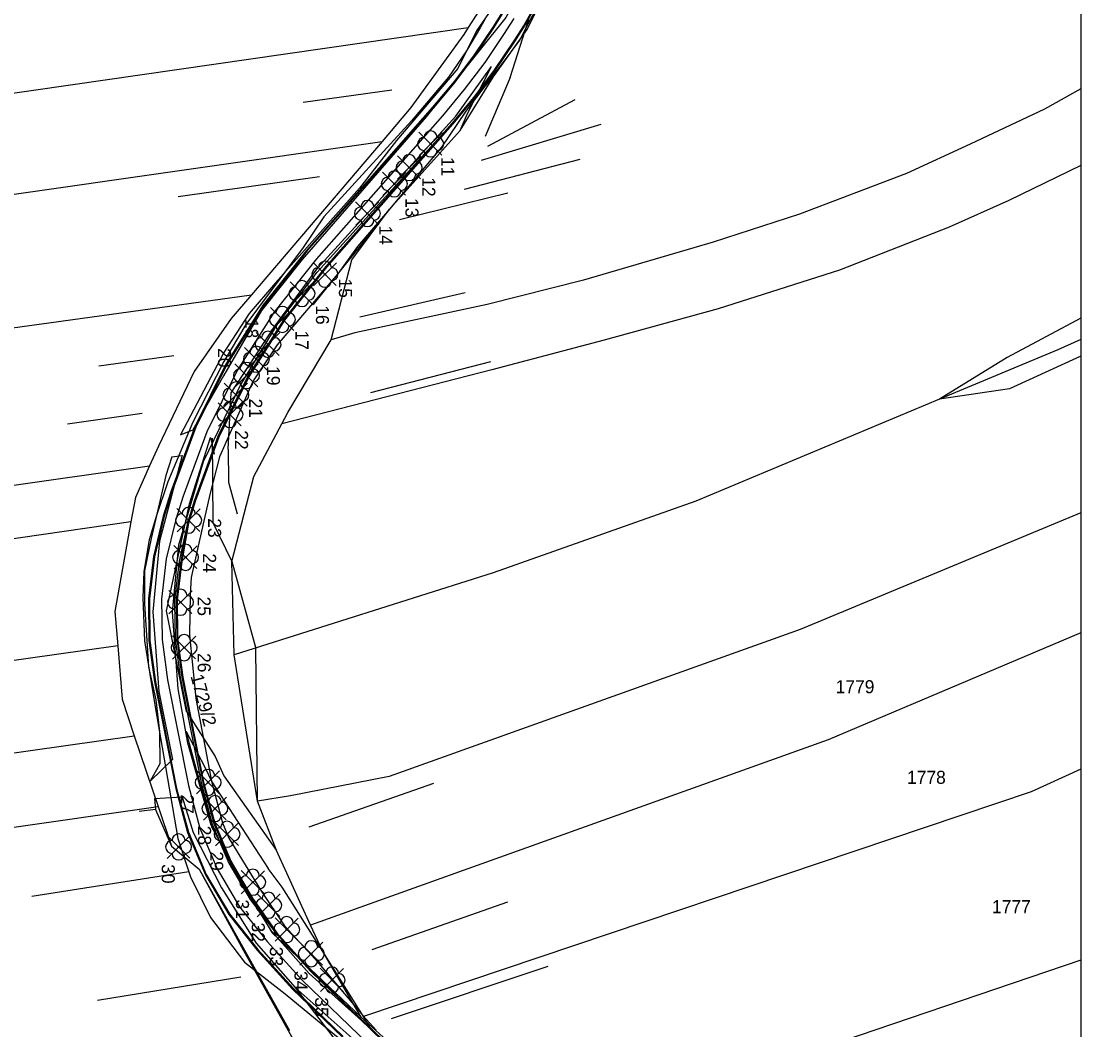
# Model space of a CAD drawing. Extents: x -601800 to -601487, y -1201912 to -1200862.
# Drawn here: x -601649.2 to -601486.7, y -1201238.4 to -1201083.7 of the extents above; entities that cross this region are included whole.
import ezdxf

# ---------------------------------------------------------------- set-up
doc = ezdxf.new("R2010")
doc.units = 0
for name, color, linetype in [('Hranice parcel', 7, 'Continuous'), ('Parcelní čísla', 7, 'Continuous'), ('popis', 7, 'Continuous'), ('u_hrany', 7, 'Continuous'), ('U_keř', 7, 'Continuous'), ('u_návrh', 7, 'Continuous'), ('u_osa', 7, 'Continuous'), ('u_strom', 7, 'Continuous'), ('u_terénní úpravy', 7, 'Continuous'), ('x_rám', 7, 'Continuous')]:
    doc.layers.add(name, color=color, linetype=linetype)

msp = doc.modelspace()

# ---------------------------------------------------------------- linework, layer by layer
at = {"layer": 'Hranice parcel'}
for p, q in [((-601593.88, -1201102.11), (-601613.91, -1201125.63)), ((-601783.66, -1201173.9), (-601629.54, -1201151.87)), ((-601632.4, -1201160.49), (-601783.66, -1201182.11)), ((-601634.44, -1201179.47), (-601783.66, -1201200.8)), ((-601612.99, -1201203.33), (-601616.59, -1201180.86)), ((-601783.66, -1201214.97), (-601631.89, -1201193.28)), ((-601631.89, -1201193.28), (-601628.22, -1201204.11)), ((-601783.66, -1201226.33), (-601628.22, -1201204.11)), ((-601595.54, -1201238.27), (-601596.75, -1201236.33))]:
    msp.add_line(p, q, dxfattribs=at)
for points in [[(-601571.88, -1201047.94), (-601570.74, -1201062.64), (-601572.44, -1201071.88), (-601580.66, -1201084.64)], [(-601576.81, -1201092.27), (-601571.6, -1201084.92), (-601566.85, -1201075.32), (-601566.81, -1201075.18)], [(-601783.66, -1201113.35), (-601714.46, -1201103.92), (-601580.66, -1201084.64)], [(-601580.66, -1201084.64), (-601581.35, -1201085.7), (-601589.47, -1201096.93), (-601593.88, -1201102.11)], [(-601595.54, -1201238.27), (-601605.07, -1201229.77), (-601610.77, -1201223.3), (-601615.91, -1201215.13), (-601620.08, -1201206.99), (-601623.67, -1201194.4), (-601625.15, -1201186.11), (-601626.02, -1201174.3), (-601625.06, -1201163.98), (-601621.25, -1201151.23), (-601615.58, -1201139.5), (-601609.8, -1201129.97), (-601603.81, -1201122.15), (-601584.37, -1201100.7), (-601576.81, -1201092.27)], [(-601601.67, -1201132.55), (-601598.51, -1201120.27), (-601592.73, -1201112.5), (-601581.87, -1201100.46), (-601576.81, -1201092.27)], [(-601486.66, -1201094.03), (-601492.25, -1201097.19), (-601503.64, -1201102.54), (-601513.42, -1201107.04), (-601529.8, -1201113.29), (-601543.07, -1201117.55), (-601562.98, -1201123.4), (-601577.77, -1201127.14), (-601598.06, -1201131.5), (-601601.67, -1201132.55)], [(-601783.66, -1201128.79), (-601712.92, -1201119.14), (-601593.88, -1201102.11)], [(-601486.66, -1201105.79), (-601497.71, -1201111.2), (-601506.84, -1201115.28), (-601523.69, -1201121.87), (-601542.28, -1201127.81), (-601559.8, -1201132.59), (-601577.05, -1201137.14), (-601609.27, -1201145.43)], [(-601783.66, -1201149.13), (-601718.74, -1201140.14), (-601613.91, -1201125.63)], [(-601613.91, -1201125.63), (-601617.03, -1201129.29), (-601622.71, -1201137.41), (-601628.18, -1201148.87), (-601629.54, -1201151.87)], [(-601486.66, -1201129.2), (-601497.94, -1201135.28), (-601508.35, -1201141.67)], [(-601609.27, -1201145.43), (-601608.36, -1201143.71), (-601601.67, -1201132.55)], [(-601486.66, -1201132.51), (-601490.19, -1201134.06), (-601508.35, -1201141.67)], [(-601486.66, -1201135.06), (-601497.59, -1201140.05), (-601508.35, -1201141.67)], [(-601508.35, -1201141.67), (-601545.72, -1201157.32), (-601576.81, -1201168.3), (-601616.59, -1201180.86)], [(-601616.59, -1201180.86), (-601616.93, -1201166.56), (-601613.57, -1201153.51), (-601609.27, -1201145.43)], [(-601629.54, -1201151.87), (-601631.73, -1201156.73), (-601632.4, -1201160.49)], [(-601486.66, -1201159.11), (-601529.7, -1201176.99), (-601592.77, -1201199.55), (-601607.91, -1201202.49), (-601612.99, -1201203.33)], [(-601632.4, -1201160.49), (-601634.87, -1201174.22), (-601634.44, -1201179.47)], [(-601486.66, -1201177.47), (-601525.44, -1201193.92), (-601604.85, -1201222.33)], [(-601634.44, -1201179.47), (-601633.78, -1201187.68), (-601631.89, -1201193.28)], [(-601486.66, -1201198.41), (-601494.28, -1201201.89), (-601596.75, -1201236.33)], [(-601628.22, -1201204.11), (-601626.16, -1201210.2), (-601621.94, -1201213.75), (-601608.09, -1201238.51)], [(-601604.85, -1201222.33), (-601610.09, -1201210.89), (-601612.99, -1201203.33)], [(-601596.75, -1201236.33), (-601602.98, -1201226.4), (-601604.85, -1201222.33)], [(-601486.66, -1201227.7), (-601575.76, -1201257.99)], [(-601575.76, -1201257.99), (-601583.56, -1201248.88), (-601595.54, -1201238.27)]]:
    msp.add_lwpolyline(points, dxfattribs=at)
at = {"layer": 'u_hrany'}
for points in [[(-601567.64, -1201054.11), (-601568.91, -1201060.36), (-601570.43, -1201066.96), (-601575.8, -1201079.91), (-601579.37, -1201085.15), (-601582.23, -1201090.92), (-601591.68, -1201101.99), (-601597.36, -1201109.27), (-601610.21, -1201123.79), (-601614.29, -1201128.53), (-601618.14, -1201134.51), (-601624.79, -1201147.13)], [(-601565.88, -1201054.02), (-601566.84, -1201062.55), (-601567.35, -1201066.39), (-601569.99, -1201074.28), (-601574.88, -1201083.12), (-601587.13, -1201098.35), (-601606.12, -1201120.23), (-601612.39, -1201128.07), (-601618.22, -1201138.07), (-601622.89, -1201146.38)], [(-601574.23, -1201092.29), (-601571.17, -1201082.7)], [(-601617.03, -1201140.66), (-601610.42, -1201130.59), (-601603.71, -1201121.52), (-601582.56, -1201098.24), (-601577.06, -1201090.61)], [(-601580.79, -1201097.85), (-601577.06, -1201090.61)], [(-601574.23, -1201092.29), (-601578.08, -1201101.35)], [(-601592.4, -1201094.26), (-601606, -1201096.15)], [(-601577.67, -1201102.82), (-601564.27, -1201095.7)], [(-601581.87, -1201100.46), (-601580.79, -1201097.85)], [(-601578.6, -1201104.97), (-601560.28, -1201099.46)], [(-601581.87, -1201100.46), (-601592.73, -1201112.5), (-601604.43, -1201127.11)], [(-601581.24, -1201109.45), (-601563.46, -1201104.84)], [(-601603.47, -1201107.56), (-601625.16, -1201110.59)], [(-601591.19, -1201114.1), (-601574.59, -1201110.02)], [(-601597.3, -1201129.03), (-601581.12, -1201125.27)], [(-601625.85, -1201134.98), (-601637.32, -1201136.61)], [(-601595.6, -1201140.62), (-601577.2, -1201135.87)], [(-601617.5, -1201149.31), (-601617.03, -1201140.66)], [(-601630.71, -1201143.86), (-601642.13, -1201145.5)], [(-601624.79, -1201147.13), (-601622.89, -1201146.38)], [(-601623.9, -1201189.57), (-601626.94, -1201174.12), (-601623.43, -1201157.73), (-601620.2, -1201147.52)], [(-601620.2, -1201147.52), (-601619.64, -1201150.1)], [(-601619.93, -1201147.64), (-601619.86, -1201160.56)], [(-601626.15, -1201150.5), (-601627.05, -1201153.34), (-601629.3, -1201163.03), (-601630.32, -1201167.99), (-601630.35, -1201173.03), (-601629.69, -1201182.73), (-601628.6, -1201187.76), (-601628.03, -1201192.62), (-601627.99, -1201197.6), (-601629.47, -1201200.24)], [(-601624.54, -1201150.28), (-601628.02, -1201163.41), (-601629.03, -1201174.27), (-601628.13, -1201186.48), (-601626.01, -1201196.91)], [(-601626.15, -1201150.5), (-601624.54, -1201150.28)], [(-601617.5, -1201149.31), (-601617.43, -1201154.4), (-601616.11, -1201159.25)], [(-601619.86, -1201160.56), (-601616.93, -1201166.56), (-601613.25, -1201179.88)], [(-601610.09, -1201210.89), (-601612.99, -1201203.33), (-601613.25, -1201179.88)], [(-601623.9, -1201189.57), (-601619.5, -1201196.44)], [(-601623.94, -1201192.61), (-601621.05, -1201198.08)], [(-601566.78, -1201268.44), (-601572.76, -1201260.92), (-601583.6, -1201248.74), (-601597.1, -1201236.47), (-601610.74, -1201223.52), (-601619.92, -1201207.39), (-601623.94, -1201192.61)], [(-601629.47, -1201200.24), (-601626.01, -1201196.91)], [(-601619.5, -1201196.44), (-601618.14, -1201199.44), (-601610.09, -1201210.89)], [(-601621.05, -1201198.08), (-601619.99, -1201200.37), (-601611.36, -1201213.65)], [(-601605.06, -1201207.28), (-601585.93, -1201200.55)], [(-601628.77, -1201202.9), (-601624.54, -1201202.66)], [(-601624.54, -1201202.66), (-601622.88, -1201208.1), (-601618.52, -1201216.62), (-601613.18, -1201225.1), (-601607.2, -1201231.89), (-601597.53, -1201240.51), (-601585.7, -1201250.99), (-601570.84, -1201268.04), (-601567.28, -1201275.16), (-601563.64, -1201286.39)], [(-601628.77, -1201202.9), (-601628.64, -1201204.61), (-601631.13, -1201204.92)], [(-601628.64, -1201204.61), (-601626.16, -1201210.2), (-601621.94, -1201213.75), (-601615.14, -1201226.21), (-601601.18, -1201251.22)], [(-601597.1, -1201236.47), (-601602.98, -1201226.4), (-601609.22, -1201216.5), (-601611.36, -1201213.65)], [(-601623.51, -1201214.16), (-601647.59, -1201217.93)], [(-601595.37, -1201226.07), (-601574.59, -1201218.74)], [(-601592.42, -1201236.64), (-601568.39, -1201228.61)], [(-601615.54, -1201230.32), (-601637.56, -1201233.91)], [(-601607.2, -1201231.89), (-601599.12, -1201242.46), (-601589.13, -1201252.96), (-601570.11, -1201279.18), (-601565.04, -1201291.14), (-601564.82, -1201293.65)]]:
    msp.add_lwpolyline(points, dxfattribs=at)
at = {"layer": 'U_keř'}
for p, q in [((-601588.23, -1201100.69), (-601584.69, -1201104.23)), ((-601584.66, -1201100.73), (-601588.19, -1201104.26)), ((-601591.52, -1201104.32), (-601587.99, -1201107.85)), ((-601587.95, -1201104.35), (-601591.49, -1201107.89)), ((-601593.8, -1201106.82), (-601590.26, -1201110.36)), ((-601590.23, -1201106.86), (-601593.76, -1201110.39)), ((-601597.93, -1201111.37), (-601594.39, -1201114.9)), ((-601594.35, -1201111.4), (-601597.89, -1201114.94)), ((-601604.45, -1201120.68), (-601600.92, -1201124.22)), ((-601600.88, -1201120.72), (-601604.42, -1201124.25)), ((-601607.97, -1201123.66), (-601604.43, -1201127.19)), ((-601604.4, -1201123.69), (-601607.93, -1201127.23)), ((-601610.97, -1201127.61), (-601607.43, -1201131.14)), ((-601607.4, -1201127.64), (-601610.93, -1201131.18)), ((-601613.17, -1201131.44), (-601609.64, -1201134.97)), ((-601609.6, -1201131.47), (-601613.14, -1201135.01)), ((-601614.97, -1201133.71), (-601611.43, -1201137.25)), ((-601611.4, -1201133.75), (-601614.93, -1201137.28)), ((-601616.49, -1201136.22), (-601612.95, -1201139.75)), ((-601612.91, -1201136.25), (-601616.45, -1201139.79)), ((-601618.1, -1201139.18), (-601614.57, -1201142.72)), ((-601614.53, -1201139.22), (-601618.07, -1201142.75)), ((-601619.02, -1201142.22), (-601615.48, -1201145.75)), ((-601615.44, -1201142.25), (-601618.98, -1201145.79)), ((-601625.35, -1201158.43), (-601621.82, -1201161.96)), ((-601621.78, -1201158.46), (-601625.32, -1201162)), ((-601625.83, -1201164.11), (-601622.29, -1201167.65)), ((-601622.26, -1201164.15), (-601625.79, -1201167.68)), ((-601626.6, -1201171), (-601623.07, -1201174.53)), ((-601623.03, -1201171.03), (-601626.57, -1201174.57)), ((-601626.04, -1201177.96), (-601622.51, -1201181.5)), ((-601622.47, -1201178), (-601626.01, -1201181.54)), ((-601622.37, -1201198.63), (-601618.83, -1201202.17)), ((-601618.8, -1201198.67), (-601622.33, -1201202.2)), ((-601621.33, -1201202.64), (-601617.8, -1201206.18)), ((-601617.76, -1201202.68), (-601621.3, -1201206.21)), ((-601619.46, -1201206.59), (-601615.92, -1201210.12)), ((-601615.88, -1201206.62), (-601619.42, -1201210.16)), ((-601626.9, -1201208.54), (-601623.37, -1201212.07)), ((-601623.33, -1201208.57), (-601626.87, -1201212.11)), ((-601615.51, -1201213.96), (-601611.98, -1201217.49)), ((-601611.94, -1201213.99), (-601615.48, -1201217.53)), ((-601613.09, -1201217.48), (-601609.55, -1201221.02)), ((-601609.51, -1201217.52), (-601613.05, -1201221.05)), ((-601610.3, -1201221.2), (-601606.77, -1201224.74)), ((-601606.73, -1201221.24), (-601610.27, -1201224.77)), ((-601606.53, -1201224.93), (-601603, -1201228.46)), ((-601602.96, -1201224.96), (-601606.5, -1201228.5)), ((-601603.36, -1201228.95), (-601599.82, -1201232.49)), ((-601599.79, -1201228.99), (-601603.32, -1201232.52))]:
    msp.add_line(p, q, dxfattribs=at)
for centre in [(-601586.42, -1201102.5), (-601589.72, -1201106.12), (-601591.99, -1201108.63), (-601596.12, -1201113.17), (-601606.16, -1201125.46), (-601609.16, -1201129.41), (-601613.16, -1201135.52), (-601616.3, -1201140.99), (-601623.55, -1201160.23), (-601624.02, -1201165.91), (-601624.8, -1201172.8)]:
    msp.add_circle(centre, 0.1, dxfattribs=at)
for centre, start, end in [((-601587.42, -1201102.5), 90, 270), ((-601586.42, -1201101.5), 0, 180), ((-601585.42, -1201102.5), 270, 90), ((-601586.42, -1201103.5), 180, 0), ((-601590.72, -1201106.12), 90, 270), ((-601589.72, -1201105.12), 0, 180), ((-601588.72, -1201106.12), 270, 90), ((-601591.99, -1201107.63), 0, 180), ((-601592.99, -1201108.63), 90, 270), ((-601590.99, -1201108.63), 270, 90), ((-601589.72, -1201107.12), 180, 0), ((-601591.99, -1201109.63), 180, 0), ((-601596.12, -1201112.17), 0, 180), ((-601597.12, -1201113.17), 90, 270), ((-601595.12, -1201113.17), 270, 90), ((-601596.12, -1201114.17), 180, 0), ((-601607.16, -1201125.46), 90, 270), ((-601606.16, -1201124.46), 0, 180), ((-601605.16, -1201125.46), 270, 90), ((-601609.16, -1201128.41), 0, 180), ((-601606.16, -1201126.46), 180, 0), ((-601610.16, -1201129.41), 90, 270), ((-601608.16, -1201129.41), 270, 90), ((-601609.16, -1201130.41), 180, 0), ((-601613.16, -1201134.52), 0, 180), ((-601614.16, -1201135.52), 90, 270), ((-601612.16, -1201135.52), 270, 90), ((-601613.16, -1201136.52), 180, 0), ((-601616.3, -1201139.99), 0, 180), ((-601617.3, -1201140.99), 90, 270), ((-601615.3, -1201140.99), 270, 90), ((-601616.3, -1201141.99), 180, 0), ((-601623.55, -1201159.23), 0, 180), ((-601624.55, -1201160.23), 90, 270), ((-601622.55, -1201160.23), 270, 90), ((-601623.55, -1201161.23), 180, 0), ((-601625.02, -1201165.91), 90, 270), ((-601624.02, -1201164.91), 0, 180), ((-601623.02, -1201165.91), 270, 90), ((-601624.02, -1201166.91), 180, 0), ((-601625.8, -1201172.8), 90, 270), ((-601624.8, -1201171.8), 0, 180), ((-601623.8, -1201172.8), 270, 90), ((-601624.8, -1201173.8), 180, 0)]:
    msp.add_arc(centre, 1, start, end, dxfattribs=at)
at = {"layer": 'u_návrh'}
for points in [[(-601565.43, -1201036.71), (-601564.17, -1201044.12), (-601563.58, -1201049), (-601563.45, -1201053.97), (-601563.8, -1201058.87), (-601564.25, -1201062.63), (-601565.25, -1201068.31), (-601566.89, -1201073.89), (-601569.15, -1201079.26), (-601571.96, -1201084.29), (-601573.55, -1201086.79), (-601576.5, -1201091.17), (-601579.69, -1201095.42), (-601583.08, -1201099.47), (-601602.4, -1201121.39), (-601608.83, -1201129.51), (-601614.34, -1201138.22), (-601618.91, -1201147.46), (-601622.51, -1201157.17), (-601623.59, -1201160.65)], [(-601565.53, -1201037.03), (-601564.32, -1201044.14), (-601563.73, -1201049.01), (-601563.6, -1201053.96), (-601563.95, -1201058.86), (-601564.4, -1201062.61), (-601565.39, -1201068.28), (-601567.03, -1201073.84), (-601569.28, -1201079.19), (-601572.09, -1201084.21), (-601573.68, -1201086.7), (-601576.62, -1201091.08), (-601579.81, -1201095.32), (-601583.19, -1201099.37), (-601602.51, -1201121.29), (-601608.95, -1201129.42), (-601614.47, -1201138.14), (-601619.05, -1201147.4), (-601622.65, -1201157.12), (-601623.73, -1201160.61)], [(-601572.75, -1201077.5), (-601575.4, -1201082.24), (-601576.9, -1201084.6), (-601579.76, -1201088.85), (-601582.83, -1201092.93), (-601586.12, -1201096.86), (-601605.47, -1201118.82), (-601612.1, -1201127.19), (-601617.84, -1201136.26), (-601622.59, -1201145.87), (-601626.29, -1201155.88), (-601627.44, -1201159.58), (-601628.96, -1201165.79), (-601629.7, -1201172.21), (-601629.64, -1201178.67), (-601628.79, -1201185.01), (-601625.54, -1201201.39), (-601623.73, -1201208.12), (-601620.99, -1201214.62), (-601617.4, -1201220.68), (-601613.06, -1201226.15), (-601607.6, -1201232.16), (-601599.98, -1201239.49)], [(-601572.61, -1201077.56), (-601575.27, -1201082.31), (-601576.77, -1201084.68), (-601579.64, -1201088.94), (-601582.71, -1201093.02), (-601586, -1201096.96), (-601605.35, -1201118.92), (-601611.97, -1201127.28), (-601617.7, -1201136.33), (-601622.45, -1201145.93), (-601626.15, -1201155.93), (-601627.3, -1201159.62), (-601628.81, -1201165.82), (-601629.55, -1201172.22), (-601629.49, -1201178.66), (-601628.64, -1201184.99), (-601625.4, -1201201.35), (-601623.58, -1201208.08), (-601620.85, -1201214.55), (-601617.27, -1201220.6), (-601612.94, -1201226.05), (-601607.49, -1201232.05), (-601599.86, -1201239.4)], [(-601623.74, -1201160.66), (-601625.01, -1201166.5), (-601625.7, -1201172.42), (-601625.64, -1201178.38), (-601624.84, -1201184.35), (-601621.65, -1201200.47), (-601619.93, -1201206.82), (-601617.41, -1201212.81), (-601614.09, -1201218.41), (-601610.15, -1201223.62)], [(-601623.73, -1201160.61), (-601624.77, -1201166.55), (-601625.45, -1201172.44), (-601625.39, -1201178.37), (-601624.59, -1201184.31), (-601621.4, -1201200.42), (-601619.7, -1201206.74), (-601617.18, -1201212.7), (-601613.89, -1201218.26), (-601610.14, -1201223.64)], [(-601623.59, -1201160.65), (-601624.62, -1201166.57), (-601625.3, -1201172.44), (-601625.24, -1201178.36), (-601624.45, -1201184.29), (-601621.26, -1201200.38), (-601619.56, -1201206.69), (-601617.05, -1201212.63), (-601613.76, -1201218.18), (-601610.04, -1201223.52)], [(-601610.14, -1201223.64), (-601604.83, -1201229.47), (-601597.31, -1201236.72)], [(-601610.02, -1201223.54), (-601604.73, -1201229.37), (-601590.25, -1201243.3), (-601585.48, -1201248.06), (-601580.85, -1201252.98), (-601576.41, -1201258.04), (-601572.85, -1201262.23)], [(-601597.31, -1201236.72), (-601590.36, -1201243.41), (-601585.58, -1201248.16), (-601580.96, -1201253.08), (-601576.52, -1201258.14), (-601572.99, -1201262.29)]]:
    msp.add_lwpolyline(points, dxfattribs=at)
at = {"layer": 'u_osa'}
msp.add_lwpolyline([(-601573.68, -1201083.26), (-601575.23, -1201085.69), (-601578.13, -1201090.01), (-601581.26, -1201094.17), (-601584.6, -1201098.17), (-601603.93, -1201120.11), (-601610.46, -1201128.35), (-601616.09, -1201137.24), (-601620.75, -1201146.66), (-601624.4, -1201156.53), (-601625.51, -1201160.11), (-601626.99, -1201166.15), (-601627.7, -1201172.32), (-601627.64, -1201178.53), (-601626.82, -1201184.68), (-601623.59, -1201200.93), (-601621.83, -1201207.47), (-601619.2, -1201213.72), (-601615.74, -1201219.55), (-601611.53, -1201224.86), (-601606.16, -1201230.76), (-601606.16, -1201230.76), (-601591.65, -1201244.73)], dxfattribs=at)
at = {"layer": 'u_strom'}
for centre in [(-601602.65, -1201122.49), (-601611.37, -1201133.24), (-601614.68, -1201138.02), (-601617.21, -1201144.02), (-601624.24, -1201179.77), (-601620.56, -1201200.44), (-601619.53, -1201204.45), (-601617.65, -1201208.39), (-601625.1, -1201210.34), (-601613.71, -1201215.76), (-601611.28, -1201219.29), (-601608.5, -1201223.01), (-601604.73, -1201226.73), (-601601.55, -1201230.76)]:
    msp.add_circle(centre, 0.1, dxfattribs=at)
for centre, start, end in [((-601602.65, -1201121.49), 0, 180), ((-601603.65, -1201122.49), 90, 270), ((-601601.65, -1201122.49), 270, 90), ((-601602.65, -1201123.49), 180, 0), ((-601612.37, -1201133.24), 90, 270), ((-601611.37, -1201132.24), 0, 180), ((-601610.37, -1201133.24), 270, 90), ((-601611.37, -1201134.24), 180, 0), ((-601614.68, -1201137.02), 0, 180), ((-601615.68, -1201138.02), 90, 270), ((-601613.68, -1201138.02), 270, 90), ((-601614.68, -1201139.02), 180, 0), ((-601617.21, -1201143.02), 0, 180), ((-601618.21, -1201144.02), 90, 270), ((-601616.21, -1201144.02), 270, 90), ((-601617.21, -1201145.02), 180, 0), ((-601624.24, -1201178.77), 0, 180), ((-601625.24, -1201179.77), 90, 270), ((-601623.24, -1201179.77), 270, 90), ((-601624.24, -1201180.77), 180, 0), ((-601621.56, -1201200.44), 90, 270), ((-601620.56, -1201199.44), 0, 180), ((-601619.56, -1201200.44), 270, 90), ((-601620.56, -1201201.44), 180, 0), ((-601619.53, -1201203.45), 0, 180), ((-601620.53, -1201204.45), 90, 270), ((-601618.53, -1201204.45), 270, 90), ((-601619.53, -1201205.45), 180, 0), ((-601618.65, -1201208.39), 90, 270), ((-601617.65, -1201207.39), 0, 180), ((-601616.65, -1201208.39), 270, 90), ((-601625.1, -1201209.34), 0, 180), ((-601626.1, -1201210.34), 90, 270), ((-601624.1, -1201210.34), 270, 90), ((-601617.65, -1201209.39), 180, 0), ((-601625.1, -1201211.34), 180, 0), ((-601613.71, -1201214.76), 0, 180), ((-601614.71, -1201215.76), 90, 270), ((-601612.71, -1201215.76), 270, 90), ((-601613.71, -1201216.76), 180, 0), ((-601611.28, -1201218.29), 0, 180), ((-601612.28, -1201219.29), 90, 270), ((-601610.28, -1201219.29), 270, 90), ((-601611.28, -1201220.29), 180, 0), ((-601609.5, -1201223.01), 90, 270), ((-601608.5, -1201222.01), 0, 180), ((-601607.5, -1201223.01), 270, 90), ((-601608.5, -1201224.01), 180, 0), ((-601604.73, -1201225.73), 0, 180), ((-601605.73, -1201226.73), 90, 270), ((-601603.73, -1201226.73), 270, 90), ((-601604.73, -1201227.73), 180, 0), ((-601602.55, -1201230.76), 90, 270), ((-601601.55, -1201229.76), 0, 180), ((-601600.55, -1201230.76), 270, 90), ((-601601.55, -1201231.76), 180, 0)]:
    msp.add_arc(centre, 1, start, end, dxfattribs=at)
at = {"layer": 'u_terénní úpravy'}
for points in [[(-601568.96, -1201079.35), (-601571.8, -1201084.68), (-601572.75, -1201086.55), (-601576.27, -1201091.24), (-601581.01, -1201097.46), (-601584.78, -1201102.97), (-601592.73, -1201112.5), (-601597.63, -1201118.25), (-601600.68, -1201122.43), (-601609.97, -1201133.32), (-601613.67, -1201138.86), (-601618.8, -1201150.49), (-601620.3, -1201156.25), (-601621.45, -1201161.24), (-601623.15, -1201169.02), (-601623.3, -1201171.59), (-601623.41, -1201177.78), (-601622.44, -1201187.59), (-601620.06, -1201200.23), (-601618.38, -1201206.64), (-601617.37, -1201209), (-601612.35, -1201217.17), (-601608.86, -1201222.42), (-601604.16, -1201227.55), (-601596.82, -1201236.21), (-601594.79, -1201238.45)], [(-601577.98, -1201083.22), (-601578.77, -1201084.58), (-601580.9, -1201088.23), (-601583.67, -1201092.26), (-601589.37, -1201098.93), (-601602.82, -1201113.68), (-601605.99, -1201118.41), (-601614.76, -1201130.19), (-601614.76, -1201130.19), (-601618.17, -1201135.87), (-601622.89, -1201145.16), (-601624.25, -1201148.33), (-601626.76, -1201154.33), (-601628.52, -1201159.67), (-601629.59, -1201163.23), (-601630.41, -1201168.07), (-601630.58, -1201172.13), (-601630.34, -1201178.71), (-601629.32, -1201185.1), (-601628.71, -1201188.84), (-601625.2, -1201209.04), (-601625.2, -1201209.04), (-601623.27, -1201214.94), (-601620.19, -1201221.17), (-601614.96, -1201228), (-601608.73, -1201232.85), (-601600.31, -1201239.84)]]:
    msp.add_lwpolyline(points, dxfattribs=at)
at = {"layer": 'x_rám'}
msp.add_lwpolyline([(-601486.66, -1200862.35), (-601486.66, -1201912.35), (-601783.66, -1201912.35), (-601783.66, -1200862.35)], close=True, dxfattribs=at)

# ---------------------------------------------------------------- texts
at = {"layer": 'Parcelní čísla'}
msp.add_text('1729/2', height=2, rotation=285, dxfattribs=at).set_placement((-601623.29, -1201184.12))
for s, p in [('1779', (-601524.28, -1201186.76)), ('1778', (-601513.33, -1201200.66)), ('1777', (-601500.29, -1201220.5))]:
    msp.add_text(s, height=2, dxfattribs=at).set_placement(p)
at = {"layer": 'popis'}
for s, p in [('11', (-601584.8, -1201104.49)), ('12', (-601587.7, -1201107.61)), ('13', (-601590.29, -1201110.79)), ('14', (-601594.32, -1201115.01)), ('15', (-601600.5, -1201123.14)), ('16', (-601604.02, -1201127.24)), ('18', (-601614.86, -1201129.33)), ('17', (-601607.16, -1201131.12)), ('20', (-601619.05, -1201133.82)), ('19', (-601611.55, -1201136.58)), ('21', (-601614.27, -1201141.56)), ('22', (-601616.44, -1201146.42)), ('23', (-601620.57, -1201159.92)), ('24', (-601621.34, -1201165.31)), ('25', (-601622.19, -1201171.93)), ('26', (-601622.17, -1201180.59)), ('27', (-601624.76, -1201202.29)), ('28', (-601622.11, -1201207.09)), ('29', (-601620.24, -1201211.03)), ('30', (-601627.68, -1201212.98)), ('31', (-601616.29, -1201218.41)), ('32', (-601613.87, -1201221.93)), ('33', (-601611.09, -1201225.65)), ('34', (-601607.31, -1201229.37)), ('35', (-601604.14, -1201233.4))]:
    msp.add_text(s, height=2, rotation=270, dxfattribs=at).set_placement(p)

doc.saveas('drawing.dxf')
